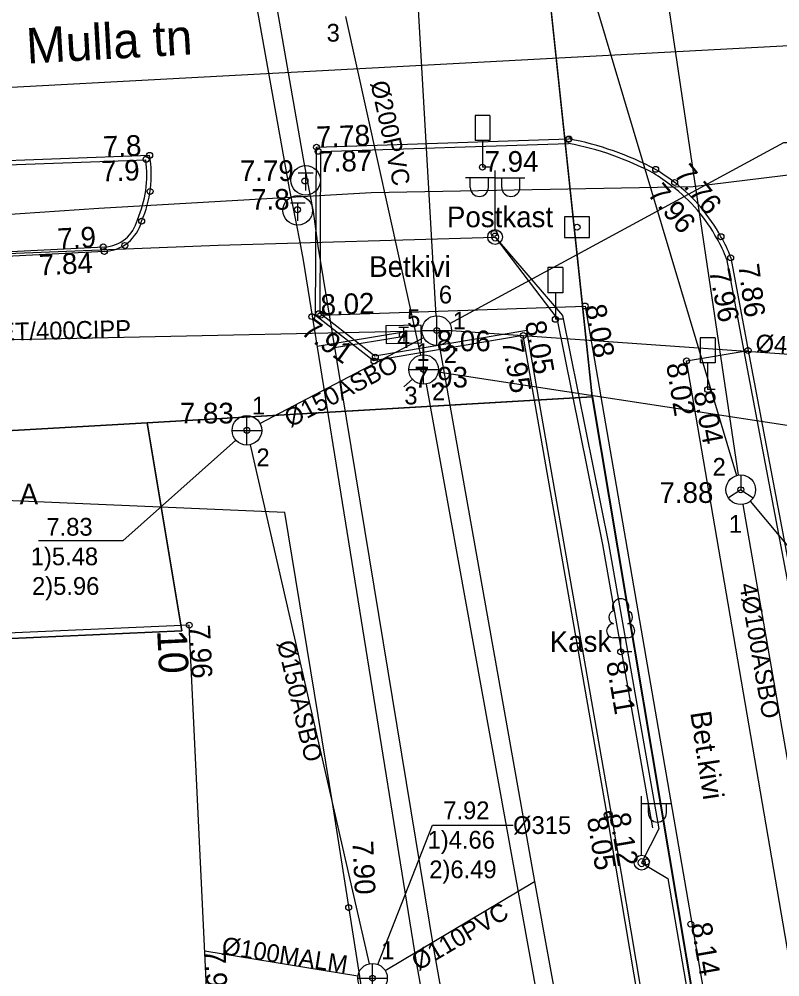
# Model space of a CAD drawing. Extents: x 473307 to 473719, y 6532843 to 6533381.
# Drawn here: x 473582.18 to 473607.89, y 6533253.2 to 6533285.57 of the extents above; entities that cross this region are included whole.
import ezdxf

# ---------------------------------------------------------------- set-up
doc = ezdxf.new("R2010")
doc.units = 0
for name, color, linetype in [('Default', 7, 'Continuous'), ('HOONE', 7, 'Continuous'), ('KKAEV', 7, 'Continuous'), ('KKAEV_NR', 7, 'Continuous'), ('KORGUS', 7, 'Continuous'), ('KPKAABEL', 7, 'Continuous'), ('KTRASS', 7, 'Continuous'), ('KTRASS_TEKST', 7, 'Continuous'), ('LIIKLUS', 7, 'Continuous'), ('MPKAABEL', 7, 'Continuous'), ('PIIR', 7, 'Continuous'), ('POST', 7, 'Continuous'), ('PUU', 7, 'Continuous'), ('RAJATIS', 7, 'Continuous'), ('SIKAEV', 7, 'Continuous'), ('SIKAEV_NR', 7, 'Continuous'), ('SITRASS', 7, 'Continuous'), ('SITRASS_TEKST', 7, 'Continuous'), ('SKKAEV', 7, 'Continuous'), ('SKKAEV_NR', 7, 'Continuous'), ('SKTRASS', 7, 'Continuous'), ('SKTRASS_TEKST', 7, 'Continuous'), ('TEE', 7, 'Continuous'), ('TKAEV', 7, 'Continuous'), ('TRAJATIS', 7, 'Continuous'), ('TTRASS', 7, 'Continuous'), ('VTRASS', 7, 'Continuous')]:
    doc.layers.add(name, color=color, linetype=linetype)

# ---------------------------------------------------------------- blocks, each defined once
blk = doc.blocks.new('KAKAEV')
at = {"layer": 'Default'}
for p, q in [((0, -1), (0, 1)), ((-1, 0), (1, 0))]:
    blk.add_line(p, q, dxfattribs=at)
blk.add_circle((0, 0), 1, dxfattribs=at)
blk = doc.blocks.new('SIKAEV')
at = {"layer": 'Default'}
for p, q in [((0, 1), (0, 0)), ((0, 0), (-0.83, -0.55)), ((0, 0), (0.83, -0.55))]:
    blk.add_line(p, q, dxfattribs=at)
blk.add_circle((0, 0), 1, dxfattribs=at)
blk = doc.blocks.new('SOKAEV')
at = {"layer": 'Default'}
for p, q in [((-0.5, 0.5), (0.5, 0.5)), ((0, -0.7), (0, 0.5))]:
    blk.add_line(p, q, dxfattribs=at)
blk.add_circle((0, 0), 1, dxfattribs=at)
blk = doc.blocks.new('LIIKLM')
at = {"layer": 'Default'}
for points in [[(-0.5, 3.5), (-0.5, 1.8)], [(0.5, 3.5), (-0.5, 3.5)], [(0.5, 3.5), (0.5, 1.8)], [(0.5, 1.8), (-0.5, 1.8)], [(0, 1.8), (0, 0)], [(0.5, 0), (0, 0)]]:
    blk.add_lwpolyline(points, dxfattribs=at)
blk = doc.blocks.new('LEHTP1')
at = {"layer": 'Default'}
for p, q in [((0.48, 0.95), (-0.48, 0.95)), ((0, 0), (0, 0.95)), ((0.76, 0), (0, 0))]:
    blk.add_line(p, q, dxfattribs=at)
for centre, radius, start, end in [((0, 3.04), 0.554, 332.5799, 207.4201), ((-0.34, 2.345), 0.465, 109.02174, 253.14154), ((0.34, 2.345), 0.465, 286.85082, 70.98591), ((-0.475, 1.425), 0.475, 90.0016, 269.3953), ((0.475, 1.425), 0.475, 270.6047, 89.9984)]:
    blk.add_arc(centre, radius, start, end, dxfattribs=at)
blk = doc.blocks.new('VAPOS2')
at = {"layer": 'Default'}
for p, q in [((0, 4), (-2, 4)), ((-1.679, 3.358), (-1.679, 4)), ((-0.453, 3.358), (-0.453, 4)), ((0, 0.5), (0, 4.5)), ((0, 4), (2, 4)), ((0.453, 3.358), (0.453, 4)), ((1.679, 3.358), (1.679, 4))]:
    blk.add_line(p, q, dxfattribs=at)
for centre in [(-1.066, 3.358), (1.066, 3.358)]:
    blk.add_arc(centre, 0.613, 180, 0, dxfattribs=at)
blk = doc.blocks.new('MEPOST')
at = {"layer": 'Default'}
blk.add_circle((0, 0), 0.5, dxfattribs=at)
for start, end in [(0, 180), (180, 0)]:
    blk.add_arc((0, 0), 0.25, start, end, dxfattribs=at)
blk = doc.blocks.new('VAPOST')
at = {"layer": 'Default'}
for p, q in [((0, 0.5), (0, 4.5)), ((0, 4), (2, 4)), ((0.453, 3.358), (0.453, 4)), ((1.679, 3.358), (1.679, 4))]:
    blk.add_line(p, q, dxfattribs=at)
blk.add_arc((1.066, 3.358), 0.613, 180, 0, dxfattribs=at)
blk = doc.blocks.new('tkilp')
at = {"layer": 'Default'}
for p, q in [((1.195, 0.597), (-1.195, 0.597)), ((-1.195, 0.597), (-1.195, -0.597)), ((1.195, -0.597), (1.195, 0.597)), ((-1.195, -0.597), (1.195, -0.597))]:
    blk.add_line(p, q, dxfattribs=at)
for points in [[(-0.324, 0.485), (0.324, 0.485)], [(0, 0.485), (0, -0.485)]]:
    blk.add_lwpolyline(points, dxfattribs=at)
blk = doc.blocks.new('rajatm')
at = {"layer": 'Default'}
blk.add_lwpolyline([(0.843, 0.702), (-0.843, 0.702), (-0.843, -0.702), (0.843, -0.702)], close=True, dxfattribs=at)

msp = doc.modelspace()

# ---------------------------------------------------------------- linework, layer by layer
at = {"layer": 'HOONE'}
msp.add_lwpolyline([(473586.451, 6533222.028), (473586.163, 6533228.83), (473590.126, 6533228.998), (473589.07, 6533252.381), (473588.538, 6533252.355), (473587.928, 6533265.086), (473574.864, 6533264.513), (473574.621, 6533270.17), (473553.465, 6533269.148), (473553.468, 6533269.088), (473497.143, 6533266.366), (473498.091, 6533246.719), (473499.996, 6533208.142), (473556.654, 6533210.892), (473555.213, 6533238.366), (473566.97, 6533238.94), (473567.826, 6533221.491), (473567.7, 6533221.486), (473567.712, 6533221.234), (473586.451, 6533222.028)], dxfattribs=at)
at = {"layer": 'KKAEV_NR'}
for points in [[(473596.732, 6533275.283), (473608.016, 6533281.398), (473610.737, 6533281.398)], [(473589.502, 6533271.339), (473585.684, 6533267.933), (473582.831, 6533267.933)], [(473594.304, 6533253.62), (473596.151, 6533258.329), (473598.872, 6533258.329)]]:
    msp.add_lwpolyline(points, dxfattribs=at)
at = {"layer": 'KORGUS'}
for centre in [(473600.757, 6533281.521), (473592.228, 6533281.242), (473600.731, 6533281.502), (473586.588, 6533280.969), (473592.282, 6533281.102), (473586.469, 6533280.834), (473597.835, 6533280.57), (473603.69, 6533280.494), (473591.838, 6533280.101), (473604.332, 6533280.048), (473586.604, 6533279.747), (473591.585, 6533279.13), (473586.319, 6533278.743), (473598.232, 6533278.329), (473601.035, 6533278.538), (473605.897, 6533278.217), (473585.022, 6533277.875), (473585.059, 6533277.719), (473585.753, 6533277.924), (473606.226, 6533277.506), (473601.305, 6533275.875), (473592.07, 6533275.517), (473592.311, 6533275.616), (473592.376, 6533275.568), (473600.3, 6533275.425), (473596.292, 6533275.045), (473595.13, 6533274.909), (473599.216, 6533274.876), (473594.215, 6533274.148), (473606.812, 6533274.373), (473594.173, 6533274.015), (473604.734, 6533274.019), (473595.847, 6533273.729), (473605.447, 6533273.05), (473589.876, 6533271.672), (473606.566, 6533269.664), (473587.928, 6533265.086), (473602.508, 6533264.184), (473602.054, 6533258.671), (473602.122, 6533258.693), (473603.383, 6533257.087), (473593.315, 6533255.543), (473604.878, 6533254.981), (473594.121, 6533253.154)]:
    msp.add_circle(centre, 0.1, dxfattribs=at)
at = {"layer": 'KPKAABEL'}
for points in [[(473615.664, 6533298.845), (473618.359, 6533285.308), (473618.229, 6533283.689), (473616.939, 6533282.082), (473615.155, 6533281.15), (473604.958, 6533279.899), (473594.081, 6533279.705), (473584.872, 6533279.168), (473575.551, 6533278.541), (473567.551, 6533277.966), (473562.423, 6533278.215), (473560.662, 6533279.216), (473558.752, 6533280.739), (473548.282, 6533291.71), (473546.684, 6533294.796)], [(473599.245, 6533215.151), (473598.214, 6533223.062), (473597.334, 6533229.753), (473596.618, 6533234.501), (473594.535, 6533247.835), (473592.795, 6533258.945), (473591.16, 6533268.89), (473578.283, 6533269.448)]]:
    msp.add_lwpolyline(points, dxfattribs=at)
at = {"layer": 'KTRASS'}
for p, q in [((473594.551, 6533253.411), (473599.595, 6533256.427)), ((473588.455, 6533254.075), (473593.628, 6533253.234))]:
    msp.add_line(p, q, dxfattribs=at)
for points in [[(473594.985, 6533297.631), (473596.263, 6533275.544)], [(473563.978, 6533274.355), (473595.792, 6533275.033)], [(473596.792, 6533275.045), (473621.69, 6533273.299)], [(473590.318, 6533271.904), (473595.85, 6533274.812)], [(473596.379, 6533274.552), (473599.595, 6533256.427), (473604.261, 6533230.713), (473605.956, 6533221.161)], [(473589.988, 6533271.184), (473594.01, 6533253.642)]]:
    msp.add_lwpolyline(points, dxfattribs=at)
at = {"layer": 'MPKAABEL'}
for points in [[(473525.948, 6533290.824), (473539.287, 6533291.718), (473545.145, 6533292.046), (473550.656, 6533292.727), (473564.851, 6533292.918), (473566.45, 6533292.671), (473568.205, 6533285.94), (473572.537, 6533278.089), (473573.477, 6533277.469), (473574.937, 6533277.378), (473588.904, 6533277.934), (473598.263, 6533278.206), (473600.541, 6533275.557), (473602.095, 6533267.853), (473603.802, 6533258.2), (473603.216, 6533257.059), (473604.096, 6533256.527), (473606.448, 6533242.906), (473608.439, 6533231.57), (473607.954, 6533230.431), (473608.769, 6533229.316), (473610.682, 6533219.295)], [(473564.851, 6533292.918), (473566.45, 6533292.671), (473568.205, 6533285.94), (473572.537, 6533278.089), (473573.477, 6533277.469), (473574.937, 6533277.378), (473588.904, 6533277.934), (473598.263, 6533278.206)], [(473598.263, 6533278.206), (473600.541, 6533275.557), (473602.095, 6533267.853), (473603.802, 6533258.2), (473603.216, 6533257.059)], [(473598.263, 6533278.206), (473600.346, 6533275.462), (473601.889, 6533267.814), (473603.583, 6533258.233)], [(473603.216, 6533257.059), (473604.096, 6533256.527), (473606.448, 6533242.906), (473608.439, 6533231.57), (473607.954, 6533230.431)]]:
    msp.add_lwpolyline(points, dxfattribs=at)
at = {"layer": 'PIIR'}
for points in [[(473678.608, 6532842.593), (473677.66, 6532847.73), (473668.24, 6532906.4), (473664.64, 6532927.81), (473654.16, 6532926.37), (473630.89, 6533065.72), (473641.36, 6533067.51), (473636.3, 6533097.55), (473618.8, 6533170.64), (473609.94, 6533222.84), (473601.54, 6533272.81), (473599.09, 6533295.91), (473592.3, 6533328.43), (473587.14, 6533353.72), (473584.47, 6533353.28), (473580.56, 6533374.06), (473585.23, 6533374.14), (473584.699, 6533380.885)], [(473306.698, 6533269.314), (473318.22, 6533273.04), (473319.15, 6533273.32), (473325.84, 6533274.58), (473345.31, 6533277.99), (473387.78, 6533284.78), (473409.45, 6533285.94), (473429.73, 6533289.19), (473430.17, 6533286.8), (473480.73, 6533288.66), (473545.58, 6533292.4), (473585.1, 6533294.7), (473599.09, 6533295.91), (473601.54, 6533272.81), (473586.5, 6533271.93), (473496.37, 6533266.79), (473372.23, 6533259.41), (473356.5, 6533258.46), (473354.97, 6533266.17), (473326.61, 6533261.28), (473306.698, 6533254.866)]]:
    msp.add_lwpolyline(points, dxfattribs=at)
for points in [[(473586.5, 6533271.93), (473601.56, 6533272.81), (473609.94, 6533222.84), (473586.39, 6533221.76), (473567.96, 6533221.17), (473565.61, 6533263.9), (473587.68, 6533264.9)], [(473496.37, 6533266.79), (473586.5, 6533271.93), (473587.68, 6533264.9), (473565.61, 6533263.9), (473567.96, 6533221.17), (473558.63, 6533220.73), (473559.2, 6533209.37), (473499.84, 6533206.38)]]:
    msp.add_lwpolyline(points, close=True, dxfattribs=at)
at = {"layer": 'SIKAEV_NR'}
msp.add_lwpolyline([(473606.886, 6533269.28), (473608.904, 6533266.87), (473614.058, 6533266.87)], dxfattribs=at)
at = {"layer": 'SITRASS'}
for points in [[(473606.492, 6533270.158), (473603.192, 6533292.394), (473601.985, 6533298.042)], [(473599.114, 6533294.62), (473606.423, 6533270.143)], [(473619.598, 6533194.755), (473606.651, 6533269.171)]]:
    msp.add_lwpolyline(points, dxfattribs=at)
at = {"layer": 'SKKAEV_NR'}
msp.add_lwpolyline([(473596.341, 6533273.653), (473608.424, 6533271.799), (473612.279, 6533271.799)], dxfattribs=at)
at = {"layer": 'SKTRASS'}
for p, q in [((473595.18, 6533273.141), (473595.472, 6533273.398)), ((473595.936, 6533273.237), (473605.038, 6533222.949))]:
    msp.add_line(p, q, dxfattribs=at)
msp.add_lwpolyline([(473593.207, 6533285.666), (473595.739, 6533274.217)], dxfattribs=at)
at = {"layer": 'TEE'}
for points in [[(473478.407, 6533275.141), (473489.142, 6533267.682), (473489.679, 6533267.393), (473496.355, 6533267.741), (473496.15, 6533271.823), (473498.459, 6533271.93), (473499.156, 6533271.986), (473515.95, 6533272.943), (473548.31, 6533274.83), (473564.748, 6533275.784), (473568.494, 6533281.781), (473576.983, 6533282.28), (473580.524, 6533280.6), (473586.46, 6533280.814)], [(473478.494, 6533275.263), (473489.22, 6533267.81), (473489.713, 6533267.545), (473496.198, 6533267.883), (473495.992, 6533271.966), (473498.45, 6533272.08), (473499.146, 6533272.136), (473515.941, 6533273.093), (473548.301, 6533274.98), (473564.662, 6533275.929), (473568.408, 6533281.926), (473577.013, 6533282.432), (473580.555, 6533280.751), (473586.588, 6533280.969)], [(473594.157, 6533274.026), (473592.197, 6533275.549), (473592.228, 6533281.242), (473600.757, 6533281.521)], [(473594.198, 6533274.185), (473592.348, 6533275.622), (473592.377, 6533281.097), (473600.745, 6533281.371)], [(473585.052, 6533277.869), (473576.926, 6533277.458), (473577.539, 6533264.63)], [(473585.059, 6533277.719), (473577.083, 6533277.316), (473577.689, 6533264.637)], [(473606.081, 6533277.468), (473606.665, 6533274.345), (473613.506, 6533238.237), (473615.579, 6533226.633)], [(473606.226, 6533277.506), (473606.812, 6533274.373), (473613.654, 6533238.264), (473613.654, 6533238.264), (473615.735, 6533226.614)], [(473592.376, 6533275.568), (473601.305, 6533275.875), (473607.974, 6533237.28), (473605.758, 6533236.896)], [(473604.75, 6533225.478), (473607.651, 6533225.971), (473606.781, 6533230.992), (473605.758, 6533236.896), (473604.961, 6533241.496), (473604.341, 6533245.074), (473603.363, 6533244.901), (473603.078, 6533246.77), (473604.03, 6533246.923), (473602.054, 6533258.671), (473599.216, 6533274.876), (473594.157, 6533274.026)], [(473604.925, 6533225.356), (473607.824, 6533225.848), (473606.929, 6533231.017), (473605.906, 6533236.922), (473605.109, 6533241.522), (473604.463, 6533245.248), (473603.488, 6533245.076), (473603.249, 6533246.645), (473604.203, 6533246.799), (473602.202, 6533258.697), (473599.338, 6533275.049), (473594.198, 6533274.185)], [(473613.654, 6533238.264), (473610.95, 6533237.796), (473604.734, 6533274.019), (473606.812, 6533274.373)]]:
    msp.add_lwpolyline(points, dxfattribs=at)
for centre, radius, start, end in [((473598.82, 6533271.29), 10.263, 62.1491, 79.1909), ((473598.82, 6533271.29), 10.413, 62.118, 79.283), ((473582.719, 6533280.307), 3.925, 336.512, 9.707), ((473582.719, 6533280.307), 3.775, 336.327, 7.7194), ((473599.206, 6533273.353), 8.282, 52.5596, 57.8357), ((473599.206, 6533273.353), 8.432, 52.5596, 57.8741), ((473600.815, 6533275.458), 5.783, 28.499, 52.5393), ((473600.815, 6533275.458), 5.633, 28.4635, 52.539), ((473584.998, 6533279.082), 1.214, 272.5586, 346.1772), ((473584.998, 6533279.082), 1.364, 272.5775, 345.6239), ((473602.839, 6533276.37), 3.422, 18.7049, 31.1895), ((473602.839, 6533276.37), 3.572, 18.5325, 31.132)]:
    msp.add_arc(centre, radius, start, end, dxfattribs=at)
at = {"layer": 'TRAJATIS'}
for points in [[(473595.164, 6533274.992), (473592.245, 6533274.512)], [(473595.189, 6533274.844), (473592.839, 6533274.458)]]:
    msp.add_lwpolyline(points, dxfattribs=at)
at = {"layer": 'TTRASS'}
for points in [[(473581.571, 6533289.506), (473582.357, 6533289.56), (473583.209, 6533289.664), (473584.017, 6533289.75), (473589.111, 6533290.209), (473589.756, 6533290.303), (473590.004, 6533290.177), (473590.22, 6533289.978), (473590.314, 6533289.259), (473591.775, 6533280.853), (473592.002, 6533279.644), (473592.11, 6533279.072), (473592.288, 6533277.816), (473592.297, 6533277.757)], [(473582.064, 6533289.054), (473583.759, 6533289.232), (473588.581, 6533289.646), (473589.192, 6533289.706), (473589.443, 6533289.57), (473589.585, 6533289.426), (473589.727, 6533288.668), (473591.303, 6533279.848), (473591.551, 6533278.61), (473591.655, 6533278.091), (473591.775, 6533277.426)], [(473592.297, 6533277.757), (473596.188, 6533254.087), (473601.84, 6533222.521), (473604, 6533210.082), (473607.02, 6533191.72), (473607.264, 6533190.194), (473603.552, 6533189.561), (473604.136, 6533186.261), (473607.868, 6533186.888), (473612.623, 6533162.34), (473616.873, 6533138.735), (473619.773, 6533121.514), (473620.151, 6533119.324)], [(473591.775, 6533277.426), (473595.59, 6533253.766), (473601.028, 6533223.219), (473603.147, 6533210.812), (473606.172, 6533192.662), (473606.51, 6533190.705), (473602.77, 6533190.028), (473603.588, 6533185.543), (473607.3, 6533186.208), (473612.067, 6533161.644), (473616.282, 6533137.983), (473619.426, 6533120.252), (473619.546, 6533119.497)]]:
    msp.add_lwpolyline(points, dxfattribs=at)
at = {"layer": 'VTRASS'}
msp.add_lwpolyline([(473353.303, 6533269.506), (473365.999, 6533272.186), (473379.745, 6533270.923), (473385.029, 6533271.056), (473412.227, 6533273.37), (473464.393, 6533276.821), (473499.973, 6533278.249), (473517.192, 6533279.473), (473556.042, 6533281.885), (473612.816, 6533284.928)], dxfattribs=at)

# ---------------------------------------------------------------- block references
at = {"layer": 'KKAEV', "xscale": 0.5, "yscale": 0.5}
for p in [(473596.292, 6533275.045), (473589.876, 6533271.672), (473594.121, 6533253.154)]:
    msp.add_blockref('KAKAEV', p, dxfattribs=at)
at = {"layer": 'LIIKLUS', "xscale": 0.5, "yscale": 0.5}
for p in [(473597.835, 6533280.57), (473600.3, 6533275.425), (473605.447, 6533273.05)]:
    msp.add_blockref('LIIKLM', p, dxfattribs=at)
at = {"layer": 'POST', "xscale": 0.5, "yscale": 0.5}
for name, p in [('VAPOS2', (473598.263, 6533278.206)), ('MEPOST', (473598.263, 6533278.206)), ('VAPOST', (473603.216, 6533257.059)), ('MEPOST', (473603.216, 6533257.059))]:
    msp.add_blockref(name, p, dxfattribs=at)
at = {"layer": 'PUU', "xscale": 0.5, "yscale": 0.5}
msp.add_blockref('LEHTP1', (473602.508, 6533264.184), dxfattribs=at)
at = {"layer": 'RAJATIS', "xscale": 0.5, "yscale": 0.5}
msp.add_blockref('rajatm', (473601.035, 6533278.538), dxfattribs=at)
at = {"layer": 'SIKAEV', "xscale": 0.5, "yscale": 0.5}
msp.add_blockref('SIKAEV', (473606.566, 6533269.664), dxfattribs=at)
at = {"layer": 'SKKAEV', "xscale": 0.5, "yscale": 0.5}
msp.add_blockref('KAKAEV', (473595.847, 6533273.729), dxfattribs=at)
at = {"layer": 'TKAEV', "xscale": 0.5, "yscale": 0.5}
for p in [(473591.862, 6533280.124), (473591.594, 6533279.108)]:
    msp.add_blockref('SOKAEV', p, dxfattribs=at)
at = {"layer": 'TRAJATIS', "xscale": 0.49999999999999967, "yscale": 0.4999999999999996, "rotation": 1.4131026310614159}
msp.add_blockref('tkilp', (473595.177, 6533274.918), dxfattribs=at)

# ---------------------------------------------------------------- texts
at = {"layer": 'HOONE'}
msp.add_text('10', height=1, rotation=272.7407, dxfattribs=at).set_placement((473586.842, 6533264.91))
at = {"layer": 'KKAEV_NR'}
for s, p in [('6', (473596.363, 6533275.962)), ('5', (473595.292, 6533275.164)), ('1', (473596.833, 6533275.084)), ('4', (473594.947, 6533274.458)), ('2', (473596.53, 6533273.946)), ('1', (473590.048, 6533272.21)), ('2', (473590.199, 6533270.461)), ('7.83', (473583.1, 6533268.112)), ('1)5.48', (473582.572, 6533267.112)), ('2)5.96', (473582.615, 6533266.112)), ('7.92', (473596.512, 6533258.529)), ('%%c315', (473598.872, 6533258.029)), ('1)4.66', (473595.983, 6533257.533)), ('2)6.49', (473596.04, 6533256.533)), ('1', (473594.413, 6533253.796))]:
    msp.add_text(s, height=0.6, dxfattribs=at).set_placement(p)
at = {"layer": 'KORGUS'}
for s, rotation, p in [('7.78', 2.0308, (473592.228, 6533281.242)), ('7.8', 2.0695, (473585.022, 6533280.912)), ('7.87', 1.3322, (473592.298, 6533280.402)), ('7.9', 2.0695, (473584.962, 6533280.079)), ('7.76', 309.0943, (473604.284, 6533280.314)), ('7.96', 310.4096, (473603.386, 6533279.653)), ('7.9', 2.8925, (473583.491, 6533277.798)), ('7.84', 2.8925, (473582.864, 6533276.907)), ('7.96', 280.9267, (473605.492, 6533277.069)), ('7.86', 277.1934, (473606.483, 6533277.265)), ('8.02', 1.83, (473592.376, 6533275.568)), ('8.08', 280.037, (473601.305, 6533275.875)), ('7.91', 324.4434, (473591.663, 6533274.948)), ('8.05', 280.1242, (473599.27, 6533275.318)), ('7.95', 279.9059, (473598.494, 6533274.682)), ('8.02', 279.3113, (473604.043, 6533273.906)), ('8.04', 280.603, (473604.966, 6533272.948)), ('7.96', 272.7407, (473587.928, 6533265.086)), ('8.11', 279.8029, (473602.012, 6533263.824)), ('8.12', 279.5495, (473602.122, 6533258.693)), ('8.05', 279.5495, (473601.363, 6533258.555)), ('7.90', 272.7258, (473593.442, 6533257.785)), ('8.14', 279.8029, (473604.878, 6533254.981)), ('7.98', 272.7226, (473588.454, 6533254.123))]:
    msp.add_text(s, height=0.7, rotation=rotation, dxfattribs=at).set_placement(p)
for s, p in [('7.94', (473597.908, 6533280.412)), ('7.79', (473589.638, 6533280.101)), ('7.8', (473590.019, 6533279.13)), ('8.06', (473596.292, 6533274.345)), ('7.93', (473595.526, 6533273.12)), ('7.83', (473587.609, 6533271.905)), ('7.88', (473603.819, 6533269.219))]:
    msp.add_text(s, height=0.7, dxfattribs=at).set_placement(p)
at = {"layer": 'KTRASS_TEKST'}
for s, rotation, p in [('%%C400BET/400CIPP', 1.3367, (473579.012, 6533274.642)), ('%%C400BET/400CIPP', 355.9594, (473607.048, 6533274.328)), ('%%c150ASBO', 27.9231, (473591.345, 6533271.758)), ('%%c150ASBO', 283.4348, (473590.884, 6533264.497)), ('%%c110PVC', 30.5873, (473595.669, 6533253.392)), ('%%c100MALM', 351.2145, (473588.999, 6533253.969))]:
    msp.add_text(s, height=0.6, rotation=rotation, dxfattribs=at).set_placement(p)
at = {"layer": 'PUU'}
msp.add_text('Kask', height=0.7, dxfattribs=at).set_placement((473600.108, 6533264.184))
at = {"layer": 'RAJATIS'}
msp.add_text('Postkast', height=0.7, dxfattribs=at).set_placement((473596.635, 6533278.538))
at = {"layer": 'SIKAEV_NR'}
for s, p in [('2', (473605.613, 6533270.139)), ('1', (473606.164, 6533268.208))]:
    msp.add_text(s, height=0.6, dxfattribs=at).set_placement(p)
at = {"layer": 'SITRASS_TEKST'}
msp.add_text('4%%c100ASBO', height=0.6, rotation=279.8694, dxfattribs=at).set_placement((473606.514, 6533266.461))
at = {"layer": 'SKKAEV_NR'}
for s, p in [('3', (473592.57, 6533284.812)), ('1', (473595.604, 6533274.019)), ('2', (473596.135, 6533272.686)), ('3', (473595.197, 6533272.548))]:
    msp.add_text(s, height=0.6, dxfattribs=at).set_placement(p)
at = {"layer": 'SKTRASS_TEKST'}
msp.add_text('%%c200PVC', height=0.6, rotation=282.4719, dxfattribs=at).set_placement((473594.046, 6533283.421))
at = {"layer": 'TEE'}
for s, height, rotation, p in [('Mulla tn', 1.2, 3.2461, (473582.451, 6533284.066)), ('Bet.kivi', 0.7, 278.5561, (473604.857, 6533262.132))]:
    msp.add_text(s, height=height, rotation=rotation, dxfattribs=at).set_placement(p)
for s, p in [('Betkivi', (473594.009, 6533276.859)), ('A', (473582.196, 6533269.168))]:
    msp.add_text(s, height=0.7, dxfattribs=at).set_placement(p)

doc.saveas('drawing.dxf')
